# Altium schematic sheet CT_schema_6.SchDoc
size 387 x 301 mm
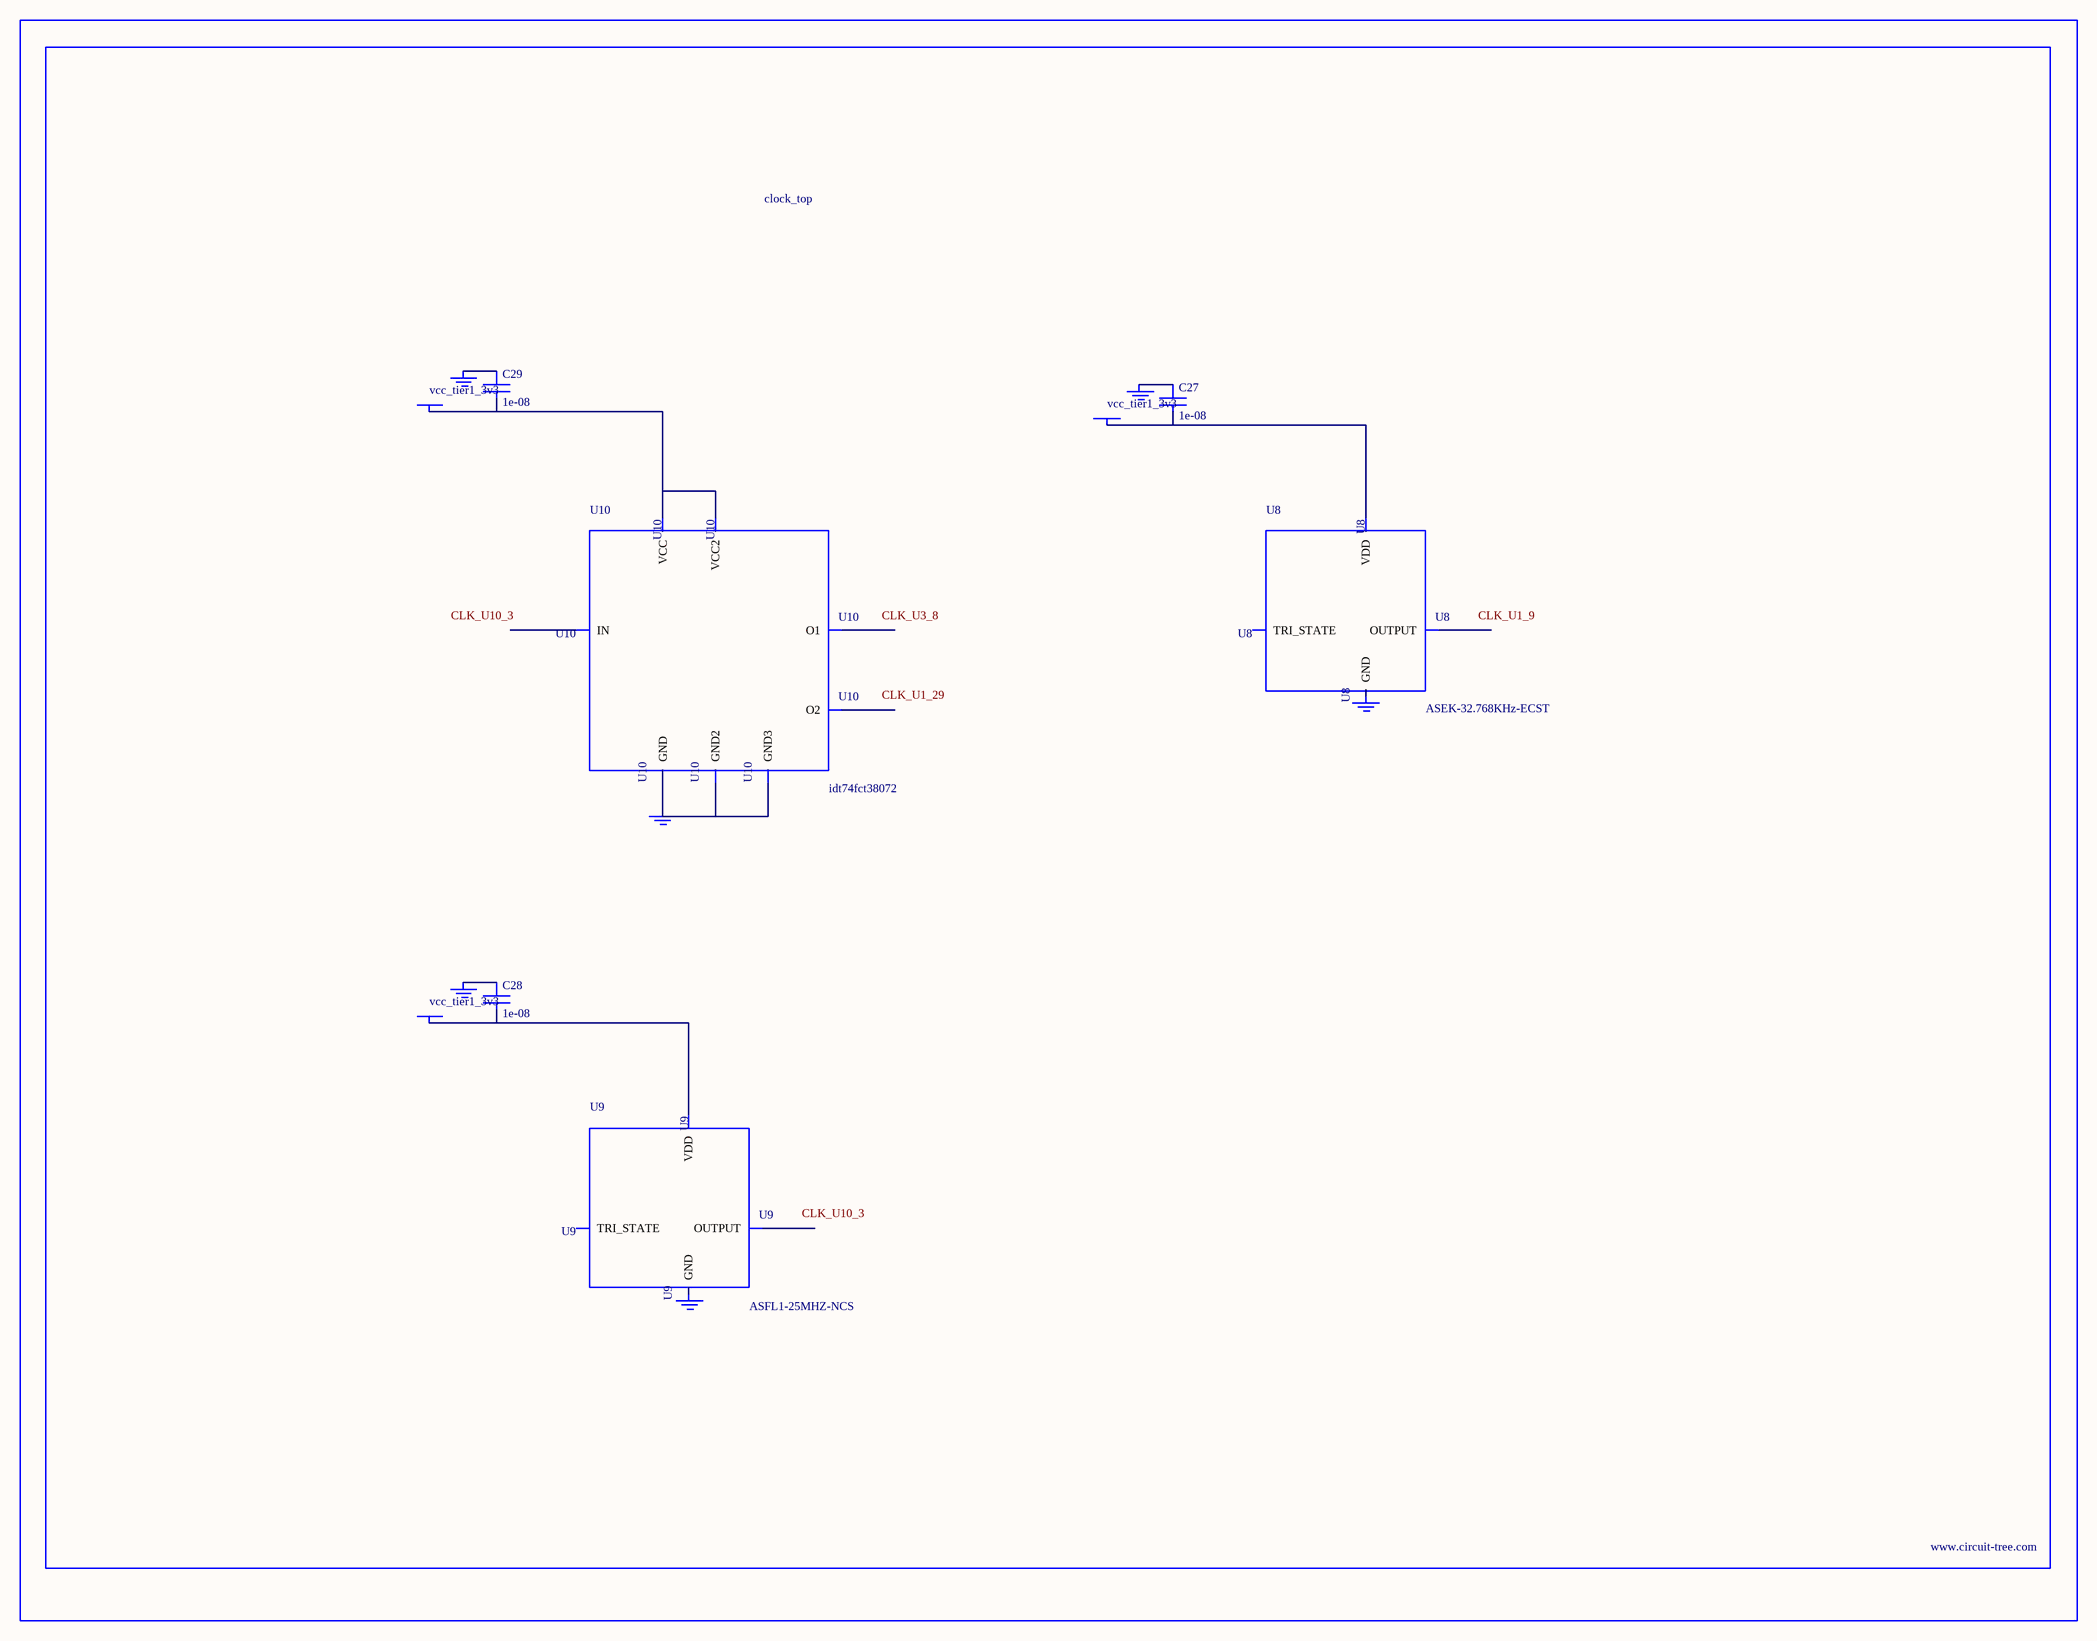
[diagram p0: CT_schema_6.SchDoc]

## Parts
BORDER5  (no value)
C27  1e-08  [C0402]
C28  1e-08  [C0402]
C29  1e-08  [C0402]
GND_INSTANCE_5_0  (no value)
GND_INSTANCE_5_1  (no value)
GND_INSTANCE_5_2  (no value)
GND_INSTANCE_5_3  (no value)
GND_INSTANCE_5_4  (no value)
GND_INSTANCE_5_5  (no value)
POWER_INSTANCE_5_0  vcc_tier1_3v3
POWER_INSTANCE_5_1  vcc_tier1_3v3
POWER_INSTANCE_5_2  vcc_tier1_3v3
U8  ASEK-32.768KHz-ECST  [ASEK]
U9  ASFL1-25MHZ-NCS  [ASFL1]
U10  idt74fct38072  [IDT74FCT38072]

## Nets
NetC27_1: C27.1 GND_INSTANCE_5_0.0(GND)
NetC27_2: C27.2 POWER_INSTANCE_5_0.0(PWR) U8.4(VDD)
NetC28_1: C28.1 GND_INSTANCE_5_2.0(GND)
NetC28_2: C28.2 POWER_INSTANCE_5_1.0(PWR) U9.4(VDD)
NetC29_1: C29.1 GND_INSTANCE_5_4.0(GND)
NetC29_2: C29.2 POWER_INSTANCE_5_2.0(PWR) U10.1(VCC) U10.2(VCC2)
NetGND_INSTANCE_5_5_0: GND_INSTANCE_5_5.0(GND) U10.4(GND) U10.5(GND2) U10.8(GND3)

Not connected (* = marked no-connect by the designer): GND_INSTANCE_5_1 0(GND); GND_INSTANCE_5_3 0(GND); U8 1(TRI_STATE) 2(GND) 3(OUTPUT); U9 1(TRI_STATE) 2(GND) 3(OUTPUT); U10 3(IN) 6(O2) 7(O1)

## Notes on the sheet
- Labels drawn without touching a wire or pin: CLK_U1_9, CLK_U1_29, CLK_U3_8, CLK_U10_3

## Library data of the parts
BORDER5 = BORDER_PAGE5
C27-C29 = C0402C103K3RAC
GND_INSTANCE_5_0-GND_INSTANCE_5_5 = GND
POWER_INSTANCE_5_0-POWER_INSTANCE_5_2 = PWR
